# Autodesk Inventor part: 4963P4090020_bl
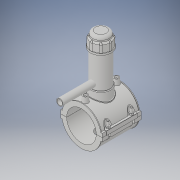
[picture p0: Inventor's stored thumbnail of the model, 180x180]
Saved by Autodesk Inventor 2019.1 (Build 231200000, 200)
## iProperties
Created: 2017-07
Part Number: 4963P4090020_bl
Material: Generic
Document SubType Name: Modeling
Designer: KIM
Density: 1 g/cm^3
Appearance: Default
Author: KIM
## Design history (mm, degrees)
derived "4963P4.ipt"
feature "Solid1::4963P4.ipt" dims "ScaleForDerivedMember" = 10
feature "Solid2::4963P4.ipt" dims "ScaleForDerivedMember" = 10
feature "Solid3::4963P4.ipt" dims "ScaleForDerivedMember" = 10
tag "TaggingFeature1"
body "Solid1"
body "Solid2"
body "Solid3"
other parameters: "d2" = 126 [user parameter], "d3" = 22.5 [user parameter], "d4" = 118 [user parameter], "d5" = 0 [user parameter], "d6" = 0.1 [user parameter], "d8" = 0 [user parameter], "d19" = 6 [user parameter], "d20" = 6 [user parameter], "d21" = 70.8 [user parameter], "d23" = 0 [user parameter], "d24" = 35.4 [user parameter], "d26" = 0 [user parameter], "d27" = 3 [user parameter], "d28" = 3 [user parameter], "d29" = 3 [user parameter], "d31" = 6 [user parameter], "d32" = 0 [user parameter], "d33" = 0 [user parameter], "d34" = 0.6 [user parameter], "d40" = 60.84 [user parameter], "d41" = 63 [user parameter], "d43" = 0 [user parameter], "d45" = 0 [user parameter], "d47" = 129.3 [user parameter], "d70" = 15 [user parameter], "d72" = 0 [user parameter], "d73" = 6 [user parameter], "d75" = 5 [user parameter], "d76" = 0 [user parameter], "d77" = 4.5 [user parameter], "d78" = 75 [user parameter], "d79" = 15 [user parameter], "d80" = 47.2 [user parameter], "d82" = 5 deg [user parameter], "d84" = 4 [user parameter], "d85" = 14 [user parameter], "d86" = 0 [user parameter], "d87" = 3 [user parameter], "d88" = 0 [user parameter], "d89" = 1 [user parameter], "d90" = 1 [user parameter], "d91" = 94.4 [user parameter], "d92" = 0 [user parameter], "d93" = 0.5 [user parameter], "d94" = 47.36842 [user parameter], "d96" = 119.34 [user parameter], "d97" = 2.36 [user parameter], "d98" = 0 [user parameter], "d102" = 0.9 [user parameter], "d120" = 140 deg [user parameter], "d121" = 24.228 [user parameter], "d122" = 20 deg [user parameter], "d123" = 234 [user parameter], "d124" = 70.2 [user parameter], "d126" = 0 [user parameter], "d143" = 92.7 [user parameter], "d145" = 20.76923 [user parameter], "d149" = 1.35 [user parameter], "d150" = 22.84615 [user parameter], "d153" = 118 [user parameter], "d154" = 0 [user parameter], "d156" = 58.5 [user parameter], "d157" = 160 deg [user parameter], "d159" = 5.4 [user parameter], "d161" = 1.35 [user parameter], "d162" = 70.8 [user parameter], "d163" = 0 [user parameter], "d164" = 45 [user parameter], "d167" = 9 [user parameter], "d168" = 57.07317 [user parameter], "d170" = 3.75 [user parameter], "d172" = 0 [user parameter], "d173" = 1 [user parameter], "d175" = 45 [user parameter], "d176" = 20 deg [user parameter], "d177" = 6.3 [user parameter], "d178" = 27 [user parameter], "d180" = 0 [user parameter], "d183" = 10.8 [user parameter], "d184" = 5.04 [user parameter], "d185" = 38.35 [user parameter], "d186" = 38.35 [user parameter], "d187" = 58.5 [user parameter], "d188" = 8.1 [user parameter], "d189" = 6.3 [user parameter], "d190" = 0 [user parameter], "d191" = 87.75 [user parameter], "d193" = 8 [user parameter], "d194" = 4.13 [user parameter], "d195" = 90 deg [user parameter], "d197" = 0 [user parameter], "d199" = 0 [user parameter], "d200" = 13.5 [user parameter], "d202" = 0 [user parameter], "d203" = 177 [user parameter], "d204" = 59.85 [user parameter], "d205" = 44.1 [user parameter], "d206" = 53.55 [user parameter], "d207" = 132.75 [user parameter], "d208" = 138.06 [user parameter], "d209" = 164.61 [user parameter], "d210" = 54.18 [user parameter], "d211" = 63 [user parameter], "d212" = 50.4 [user parameter], "d213" = 36 [user parameter], "d216" = 0 [user parameter], "d217" = 9 [user parameter], "d218" = 9 [user parameter], "d219" = 1.8 [user parameter], "d224" = 0 [user parameter], "d227" = 16 [user parameter], "d228" = 125 [user parameter], "d230" = 5.4 [user parameter], "B_" = 126 [user parameter], "L_" = 118 [user parameter], "d_t" = 6 [user parameter], "H_2" = 177 [user parameter], "H_" = 125 [user parameter], "d1" = 117 [user parameter], "d148" = 1.35 [user parameter]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
